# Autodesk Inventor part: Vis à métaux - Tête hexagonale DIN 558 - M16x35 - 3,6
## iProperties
Created: 2002-04
Part Number: Vis à métaux - Tête hexagonale DIN 558 - M16x35 - 3,6
Material: Par défaut
Catalog Web Link: www.traceparts.com
Description: Vis à métaux - Tête hexagonale DIN 558 - M16x35 - 3,6
Document SubType Name: Modélisation
Designer: Maison
Control State: 0
Master: False
Checked Out: False
Shininess: 20.0
Length Units: 11269
Angle Units: 11279
Time Units: 11290
Mass Units: 11283
Length Display Precision: 3
Angle Display Precision: 2
Density: 0.0
Volumn: 0.0
Area: 0.0
PropertySet Name: Model Information
Author: Maison
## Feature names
1. Base1
